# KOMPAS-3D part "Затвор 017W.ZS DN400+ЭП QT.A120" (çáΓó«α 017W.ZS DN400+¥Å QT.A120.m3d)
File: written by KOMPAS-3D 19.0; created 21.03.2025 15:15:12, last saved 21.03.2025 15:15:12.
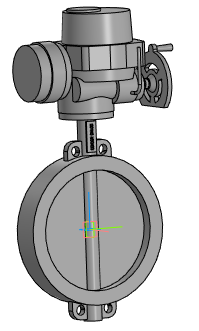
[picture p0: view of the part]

Document properties: Полное имя файла: Затвор 017W.ZS DN400+ЭП QT.A120.a3d

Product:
- Part/product: Затвор 017W.ZS DN400+ЭП QT.A120
    Масса: 225.618

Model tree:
1. Операция без истории:1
